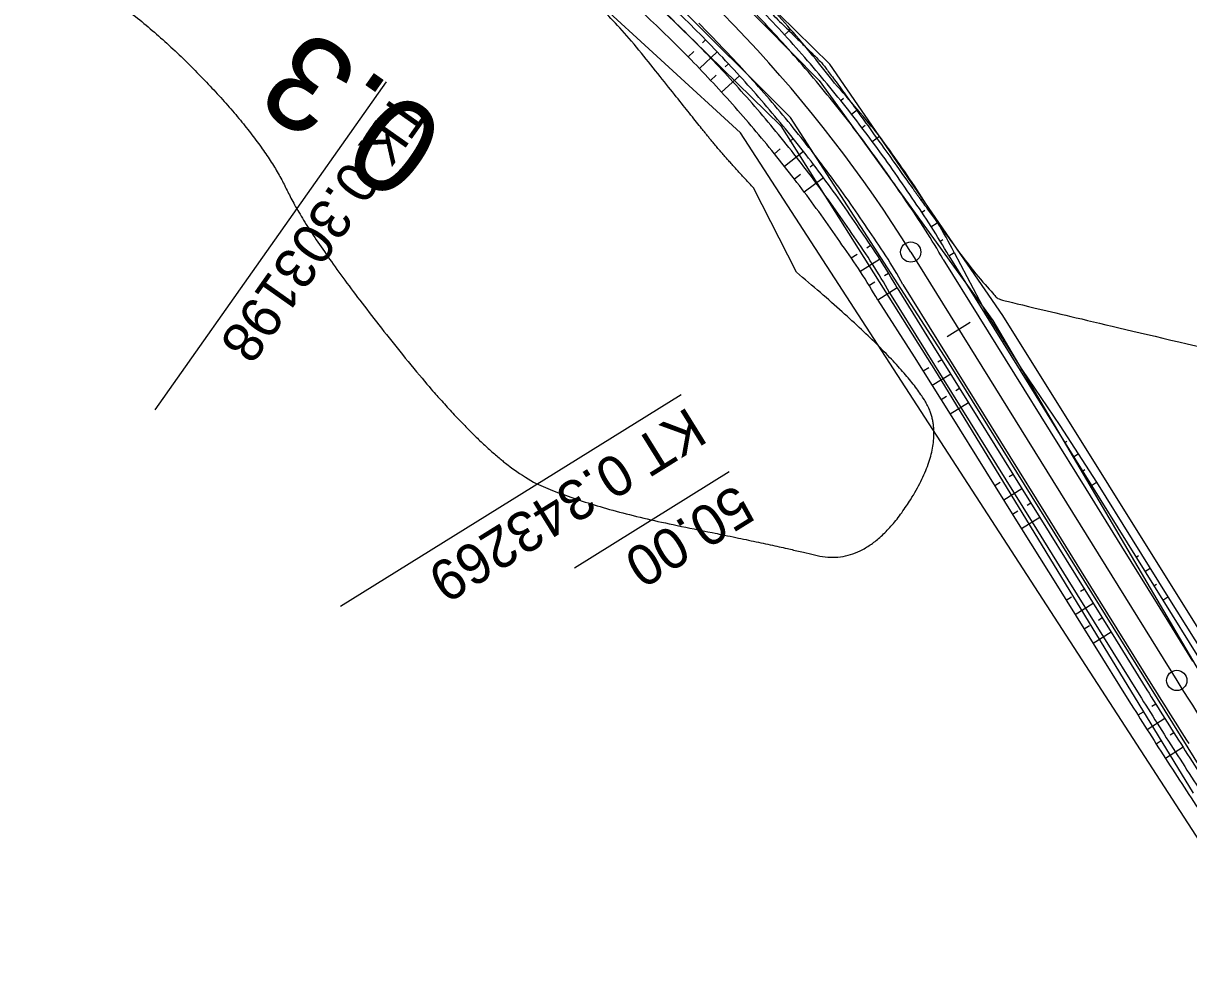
# Model space of a CAD drawing. Extents: x -495905 to -478420, y -1113297 to -1107716.
# Drawn here: x -480763.1 to -480676.8, y -1112853.9 to -1112783.6 of the extents above; entities that cross this region are included whole.
import ezdxf

# ---------------------------------------------------------------- set-up
doc = ezdxf.new("R2010")
doc.units = 0
for name, color, linetype in [('03_PC_OBJEKTY_NÁVRH_PR', 7, 'Continuous'), ('2D_VRSTEVNICE', 7, 'Continuous'), ('C13_HATCH_SLOPE_L', 7, 'Continuous'), ('C13_HATCH_SLOPE_R', 7, 'Continuous'), ('C13_HECTOMETRY', 7, 'Continuous'), ('C13_HLBODY', 7, 'Continuous'), ('C13_HRANA_TELESO', 7, 'Continuous'), ('C13_KORUNA', 7, 'Continuous'), ('C13_OSA', 7, 'Continuous'), ('C13_PRIKOP', 7, 'Continuous'), ('C13_STANICENI', 7, 'Continuous'), ('C13_VOZOVKA', 7, 'Continuous'), ('C13_ZPEVKRAJ', 7, 'Continuous'), ('zamereni', 7, 'Continuous')]:
    doc.layers.add(name, color=color, linetype=linetype)

msp = doc.modelspace()

# ---------------------------------------------------------------- linework, layer by layer
at = {"layer": '03_PC_OBJEKTY_NÁVRH_PR'}
msp.add_lwpolyline([(-480609.77, -1112943.11), (-480632.07, -1112906.22), (-480673.38, -1112848.12), (-480710, -1112791.67), (-480726.8, -1112776.25), (-480787.1, -1112736.87), (-480856.49, -1112680.15), (-480961.12, -1112584.33)], dxfattribs=at)
at = {"layer": '2D_VRSTEVNICE'}
msp.add_lwpolyline([(-480705.856, -1112801.984), (-480709.033, -1112795.743)], dxfattribs=at)
for points in [[(-480709.033, -1112795.743), (-480711.34, -1112793.268), (-480713.633, -1112790.394), (-480720.471, -1112781.825), (-480725.405, -1112779.135), (-480733.412, -1112773.693), (-480743.366, -1112768.241), (-480741.88, -1112762.294), (-480747.701, -1112758.269), (-480747.756, -1112758.23), (-480750.594, -1112756.204), (-480750.824, -1112756.04), (-480756.969, -1112751.652), (-480757.518, -1112751.261), (-480777.842, -1112736.752), (-480779.086, -1112735.864), (-480779.423, -1112735.624), (-480783.574, -1112732.66), (-480788.757, -1112728.437)], [(-480809.7, -1112754.66), (-480782.38, -1112767.95), (-480764.439, -1112762.001), (-480767.966, -1112775.097), (-480755.599, -1112781.764), (-480745.361, -1112792.13), (-480741.836, -1112799.587), (-480728.591, -1112816.095), (-480720.89, -1112819.47), (-480707.793, -1112822.109), (-480700.856, -1112823.771), (-480695.042, -1112815.483), (-480696.658, -1112809.693), (-480705.856, -1112801.984)], [(-480714.503, -1112776.18), (-480704.556, -1112785.911), (-480703.578, -1112786.898), (-480691.565, -1112803.76), (-480689.92, -1112804.25), (-480656.601, -1112812.049)]]:
    msp.add_open_spline(points, degree=2, dxfattribs=at)
at = {"layer": 'C13_HATCH_SLOPE_L'}
for p, q in [((-480706.731, -1112784.421), (-480706.281, -1112784.012)), ((-480702.578, -1112789.277), (-480702.376, -1112789.116)), ((-480702.175, -1112788.954), (-480702.175, -1112788.954)), ((-480701.784, -1112790.279), (-480701.339, -1112789.931)), ((-480701.003, -1112791.291), (-480700.759, -1112791.105)), ((-480700.515, -1112790.919), (-480700.515, -1112790.919)), ((-480700.235, -1112792.312), (-480699.702, -1112791.917)), ((-480696.089, -1112797.235), (-480696.089, -1112797.235)), ((-480696.588, -1112797.559), (-480696.338, -1112797.397)), ((-480695.899, -1112798.635), (-480695.429, -1112798.339)), ((-480695.227, -1112799.71), (-480695.008, -1112799.574)), ((-480694.79, -1112799.438), (-480694.79, -1112799.438)), ((-480694.567, -1112800.772), (-480694.165, -1112800.522)), ((-480691.269, -1112806.08), (-480691.218, -1112806.048)), ((-480691.166, -1112806.016), (-480691.166, -1112806.016)), ((-480690.609, -1112807.142), (-480690.5, -1112807.074)), ((-480689.949, -1112808.204), (-480689.892, -1112808.168)), ((-480689.834, -1112808.132), (-480689.834, -1112808.132)), ((-480689.29, -1112809.266), (-480689.168, -1112809.19)), ((-480685.991, -1112814.574), (-480685.831, -1112814.474)), ((-480685.671, -1112814.375), (-480685.671, -1112814.375)), ((-480685.331, -1112815.636), (-480684.992, -1112815.425)), ((-480684.672, -1112816.698), (-480684.492, -1112816.586)), ((-480684.313, -1112816.475), (-480684.313, -1112816.475)), ((-480684.012, -1112817.759), (-480683.634, -1112817.524)), ((-480680.713, -1112823.068), (-480680.52, -1112822.948)), ((-480680.328, -1112822.829), (-480680.328, -1112822.829)), ((-480680.054, -1112824.13), (-480679.667, -1112823.89)), ((-480679.394, -1112825.191), (-480679.2, -1112825.07)), ((-480679.006, -1112824.95), (-480679.006, -1112824.95)), ((-480678.734, -1112826.253), (-480678.345, -1112826.011))]:
    msp.add_line(p, q, dxfattribs=at)
at = {"layer": 'C13_HATCH_SLOPE_R'}
for p, q in [((-480712.576, -1112784.788), (-480712.814, -1112785.022)), ((-480713.46, -1112785.655), (-480713.867, -1112786.055)), ((-480711.725, -1112785.665), (-480713.032, -1112786.916)), ((-480710.886, -1112786.553), (-480711.13, -1112786.78)), ((-480711.79, -1112787.398), (-480712.207, -1112787.787)), ((-480710.058, -1112787.451), (-480711.394, -1112788.668)), ((-480707.047, -1112792.863), (-480707.486, -1112793.215)), ((-480706.088, -1112792.094), (-480706.348, -1112792.302)), ((-480705.329, -1112793.051), (-480706.737, -1112794.152)), ((-480704.583, -1112794.019), (-480704.848, -1112794.221)), ((-480705.556, -1112794.761), (-480706, -1112795.099)), ((-480703.848, -1112794.995), (-480705.274, -1112796.054)), ((-480701.366, -1112800.664), (-480701.812, -1112800.953)), ((-480700.362, -1112800.011), (-480700.642, -1112800.192)), ((-480699.702, -1112801.039), (-480701.154, -1112801.957)), ((-480699.049, -1112802.085), (-480699.332, -1112802.261)), ((-480700.056, -1112802.711), (-480700.498, -1112802.985)), ((-480698.39, -1112803.147), (-480699.828, -1112804.04)), ((-480695.091, -1112808.455), (-480695.374, -1112808.631)), ((-480696.062, -1112809.059), (-480696.468, -1112809.311)), ((-480694.431, -1112809.517), (-480695.802, -1112810.369)), ((-480693.772, -1112810.579), (-480694.055, -1112810.755)), ((-480694.738, -1112811.179), (-480695.137, -1112811.427)), ((-480693.112, -1112811.641), (-480694.471, -1112812.485)), ((-480689.813, -1112816.949), (-480690.096, -1112817.125)), ((-480690.772, -1112817.545), (-480691.165, -1112817.789)), ((-480689.154, -1112818.011), (-480690.506, -1112818.851)), ((-480689.454, -1112819.668), (-480689.847, -1112819.913)), ((-480688.494, -1112819.073), (-480688.777, -1112819.248)), ((-480687.834, -1112820.134), (-480689.187, -1112820.975)), ((-480684.536, -1112825.443), (-480684.819, -1112825.619)), ((-480685.488, -1112826.035), (-480685.875, -1112826.275)), ((-480683.876, -1112826.505), (-480685.212, -1112827.335)), ((-480684.166, -1112828.156), (-480684.549, -1112828.395)), ((-480683.216, -1112827.566), (-480683.499, -1112827.742)), ((-480682.556, -1112828.628), (-480683.887, -1112829.455)), ((-480679.255, -1112833.941), (-480679.538, -1112834.118)), ((-480680.194, -1112834.528), (-480680.569, -1112834.761)), ((-480678.585, -1112835.007), (-480679.893, -1112835.832)), ((-480677.912, -1112836.072), (-480678.193, -1112836.25)), ((-480678.844, -1112836.664), (-480679.213, -1112836.9)), ((-480677.233, -1112837.133), (-480678.529, -1112837.964))]:
    msp.add_line(p, q, dxfattribs=at)
at = {"layer": 'C13_HLBODY'}
for p, q in [((-480736.232, -1112787.884), (-480753.346, -1112812.157)), ((-480714.38, -1112811.045), (-480739.606, -1112826.72))]:
    msp.add_line(p, q, dxfattribs=at)
for centre in [(-480697.392, -1112800.489), (-480677.695, -1112832.188)]:
    msp.add_circle(centre, 0.75, dxfattribs=at)
at = {"layer": 'C13_HRANA_TELESO'}
for p, q in [((-480694.165, -1112800.522), (-480691.832, -1112804.958)), ((-480699.828, -1112804.04), (-480697.134, -1112808.253)), ((-480691.832, -1112804.958), (-480689.168, -1112809.19)), ((-480697.134, -1112808.253), (-480694.471, -1112812.485)), ((-480689.168, -1112809.19), (-480686.35, -1112813.326)), ((-480694.471, -1112812.485), (-480691.824, -1112816.727)), ((-480686.35, -1112813.326), (-480683.634, -1112817.524)), ((-480691.824, -1112816.727), (-480689.187, -1112820.975)), ((-480683.634, -1112817.524), (-480680.99, -1112821.768)), ((-480689.187, -1112820.975), (-480686.537, -1112825.215)), ((-480680.99, -1112821.768), (-480678.345, -1112826.011)), ((-480686.537, -1112825.215), (-480683.887, -1112829.455)), ((-480678.345, -1112826.011), (-480675.701, -1112830.255)), ((-480683.887, -1112829.455), (-480681.237, -1112833.695))]:
    msp.add_line(p, q, dxfattribs=at)
for centre, radius, start, end in [((-480783.464, -1112852.063), 102.899, 41.4022, 44.26736), ((-480782.424, -1112853.178), 95.944, 45.11065, 47.97544), ((-480784.143, -1112851.115), 102.788, 37.88976, 40.75562), ((-480782.308, -1112853.29), 95.942, 42.34173, 45.20652), ((-480779.855, -1112856.31), 102.815, 38.77783, 41.6447), ((-480782.2, -1112853.417), 95.947, 39.57666, 42.44146), ((-480782.642, -1112852.822), 102.9, 33.42609, 36.29092), ((-480782.068, -1112853.601), 95.963, 36.8472, 39.71202), ((-480781.927, -1112853.835), 95.991, 34.14437, 37.00923), ((-480739.666, -1112824.522), 51.443, 27.81079, 33.48765), ((-480741.349, -1112828.131), 48.004, 30.12239, 35.93747), ((-479910.26, -1112347.705), 911.368, 212.2255, 212.543347), ((-480423.024, -1112673.635), 303.787, 212.74733, 213.70226)]:
    msp.add_arc(centre, radius, start, end, dxfattribs=at)
at = {"layer": 'C13_KORUNA'}
for p, q in [((-480694.567, -1112800.772), (-480691.929, -1112805.019)), ((-480698.39, -1112803.147), (-480695.751, -1112807.394)), ((-480691.929, -1112805.019), (-480689.29, -1112809.266)), ((-480695.751, -1112807.394), (-480693.112, -1112811.641)), ((-480689.29, -1112809.266), (-480686.651, -1112813.512)), ((-480693.112, -1112811.641), (-480690.473, -1112815.887)), ((-480686.651, -1112813.512), (-480684.012, -1112817.759)), ((-480690.473, -1112815.887), (-480687.834, -1112820.134)), ((-480684.012, -1112817.759), (-480681.373, -1112822.006)), ((-480687.834, -1112820.134), (-480685.195, -1112824.381)), ((-480681.373, -1112822.006), (-480678.734, -1112826.253)), ((-480685.195, -1112824.381), (-480682.556, -1112828.628)), ((-480678.734, -1112826.253), (-480676.095, -1112830.5)), ((-480682.556, -1112828.628), (-480679.917, -1112832.875))]:
    msp.add_line(p, q, dxfattribs=at)
for centre, radius, start, end in [((-480782.33, -1112853.267), 97.75, 45.18774, 48.05253), ((-480782.33, -1112853.267), 102.25, 42.32296, 45.18774), ((-480782.33, -1112853.267), 97.75, 42.32295, 45.18774), ((-480782.33, -1112853.267), 102.25, 39.45817, 42.32296), ((-480782.33, -1112853.267), 97.75, 39.45817, 42.32296), ((-480782.33, -1112853.267), 102.25, 36.59338, 39.45817), ((-480782.33, -1112853.267), 97.75, 36.59338, 39.45817), ((-480782.33, -1112853.267), 102.25, 33.72859, 36.59338), ((-480782.33, -1112853.267), 97.75, 33.72859, 36.59338), ((-480739.008, -1112826.047), 51.125, 29.62846, 35.3164), ((-480740.897, -1112827.269), 48.875, 29.57422, 35.35155), ((-479911.523, -1112351.455), 906.75, 212.068244, 212.386272), ((-480422.881, -1112673.855), 302.25, 212.69777, 213.6527)]:
    msp.add_arc(centre, radius, start, end, dxfattribs=at)
at = {"layer": 'C13_OSA'}
msp.add_line((-480697.392, -1112800.489), (-480677.695, -1112832.188), dxfattribs=at)
for centre, radius, start, end in [((-480782.33, -1112853.267), 100, 31.85534, 54.81438), ((-480422.88, -1112673.855), 300, 211.85533, 216.27914)]:
    msp.add_arc(centre, radius, start, end, dxfattribs=at)
at = {"layer": 'C13_PRIKOP'}
for p, q in [((-480698.956, -1112803.498), (-480696.317, -1112807.745)), ((-480696.317, -1112807.745), (-480693.678, -1112811.992)), ((-480693.678, -1112811.992), (-480691.039, -1112816.239)), ((-480691.039, -1112816.239), (-480688.4, -1112820.486)), ((-480688.4, -1112820.486), (-480685.761, -1112824.733)), ((-480685.761, -1112824.733), (-480683.122, -1112828.98)), ((-480683.122, -1112828.98), (-480680.484, -1112833.227))]:
    msp.add_line(p, q, dxfattribs=at)
for centre, radius, start, end in [((-480782.33, -1112853.267), 97.084, 45.18774, 48.05253), ((-480782.33, -1112853.267), 97.084, 42.32295, 45.18774), ((-480782.33, -1112853.267), 97.084, 39.45816, 42.32295), ((-480782.33, -1112853.267), 97.084, 36.59338, 39.45817), ((-480782.33, -1112853.267), 97.084, 33.72859, 36.59338), ((-480741.177, -1112827.45), 48.542, 29.56579, 35.35706), ((-479910.396, -1112350.744), 908.749, 212.068381, 212.386328), ((-480422.881, -1112673.855), 302.916, 212.69777, 213.6527)]:
    msp.add_arc(centre, radius, start, end, dxfattribs=at)
at = {"layer": 'C13_STANICENI'}
for p, q in [((-480694.689, -1112806.734), (-480692.99, -1112805.678)), ((-480710.827, -1112816.762), (-480722.294, -1112823.887))]:
    msp.add_line(p, q, dxfattribs=at)
at = {"layer": 'C13_VOZOVKA'}
for p, q in [((-480694.992, -1112801.036), (-480692.353, -1112805.283)), ((-480697.965, -1112802.883), (-480695.326, -1112807.13)), ((-480692.353, -1112805.283), (-480689.714, -1112809.529)), ((-480695.326, -1112807.13), (-480692.687, -1112811.377)), ((-480689.714, -1112809.529), (-480687.075, -1112813.776)), ((-480692.687, -1112811.377), (-480690.048, -1112815.624)), ((-480687.075, -1112813.776), (-480684.437, -1112818.023)), ((-480690.048, -1112815.624), (-480687.409, -1112819.87)), ((-480684.437, -1112818.023), (-480681.798, -1112822.27)), ((-480687.409, -1112819.87), (-480684.771, -1112824.117)), ((-480681.798, -1112822.27), (-480679.159, -1112826.517)), ((-480684.771, -1112824.117), (-480682.132, -1112828.364)), ((-480679.159, -1112826.517), (-480676.52, -1112830.764)), ((-480682.132, -1112828.364), (-480679.493, -1112832.611))]:
    msp.add_line(p, q, dxfattribs=at)
for centre, radius, start, end in [((-480782.33, -1112853.267), 101.75, 42.32296, 45.18774), ((-480782.33, -1112853.267), 98.25, 42.32295, 45.18774), ((-480782.33, -1112853.267), 101.75, 39.45817, 42.32296), ((-480782.33, -1112853.267), 98.25, 39.45817, 42.32296), ((-480782.33, -1112853.267), 101.75, 36.59338, 39.45817), ((-480782.33, -1112853.267), 98.25, 36.59338, 39.45817), ((-480782.33, -1112853.267), 101.75, 33.72859, 36.59338), ((-480782.33, -1112853.267), 98.25, 33.72859, 36.59338), ((-480739.218, -1112826.182), 50.875, 29.62266, 35.32014), ((-480740.687, -1112827.133), 49.125, 29.58048, 35.34747), ((-479912.368, -1112351.989), 905.25, 212.068142, 212.386231)]:
    msp.add_arc(centre, radius, start, end, dxfattribs=at)
at = {"layer": 'C13_ZPEVKRAJ'}
for p, q in [((-480694.992, -1112801.036), (-480692.353, -1112805.283)), ((-480697.965, -1112802.883), (-480695.326, -1112807.13)), ((-480692.353, -1112805.283), (-480689.714, -1112809.529)), ((-480695.326, -1112807.13), (-480692.687, -1112811.377)), ((-480689.714, -1112809.529), (-480687.075, -1112813.776)), ((-480692.687, -1112811.377), (-480690.048, -1112815.624)), ((-480687.075, -1112813.776), (-480684.437, -1112818.023)), ((-480690.048, -1112815.624), (-480687.409, -1112819.87)), ((-480684.437, -1112818.023), (-480681.798, -1112822.27)), ((-480687.409, -1112819.87), (-480684.771, -1112824.117)), ((-480681.798, -1112822.27), (-480679.159, -1112826.517)), ((-480684.771, -1112824.117), (-480682.132, -1112828.364)), ((-480679.159, -1112826.517), (-480676.52, -1112830.764)), ((-480682.132, -1112828.364), (-480679.493, -1112832.611))]:
    msp.add_line(p, q, dxfattribs=at)
for centre, radius, start, end in [((-480782.33, -1112853.267), 101.75, 42.32296, 45.18774), ((-480782.33, -1112853.267), 98.25, 42.32295, 45.18774), ((-480782.33, -1112853.267), 101.75, 39.45817, 42.32296), ((-480782.33, -1112853.267), 98.25, 39.45817, 42.32296), ((-480782.33, -1112853.267), 101.75, 36.59338, 39.45817), ((-480782.33, -1112853.267), 98.25, 36.59338, 39.45817), ((-480782.33, -1112853.267), 101.75, 33.72859, 36.59338), ((-480782.33, -1112853.267), 98.25, 33.72859, 36.59338), ((-480739.218, -1112826.182), 50.875, 29.62266, 35.32014), ((-480740.687, -1112827.133), 49.125, 29.58048, 35.34747), ((-479912.368, -1112351.989), 905.25, 212.068142, 212.386231)]:
    msp.add_arc(centre, radius, start, end, dxfattribs=at)
at = {"layer": 'zamereni'}
for p, q in [((-480703.38, -1112786.6), (-480717.03, -1112773.17)), ((-480717.82, -1112773.98), (-480704.17, -1112787.79)), ((-480706.29, -1112790.53), (-480720.03, -1112776.84)), ((-480720.74, -1112777.72), (-480707.01, -1112791.16)), ((-480690.58, -1112805.19), (-480703.38, -1112786.6)), ((-480704.17, -1112787.79), (-480691.32, -1112805.56)), ((-480707.01, -1112791.16), (-480695.43, -1112809.49)), ((-480694.4, -1112808.95), (-480706.29, -1112790.53)), ((-480691.32, -1112805.56), (-480672.09, -1112838.26)), ((-480670.56, -1112837.22), (-480690.58, -1112805.19)), ((-480675.27, -1112839.72), (-480694.4, -1112808.95)), ((-480695.43, -1112809.49), (-480676.49, -1112840.53))]:
    msp.add_line(p, q, dxfattribs=at)

# ---------------------------------------------------------------- texts
at = {"layer": 'C13_HECTOMETRY'}
msp.add_text('0.3', height=7, rotation=144.76876, dxfattribs=at).set_placement((-480731.46, -1112791.257))
at = {"layer": 'C13_HLBODY'}
for s, rotation, p in [('TK 0.303198', 234.81438, (-480735.414, -1112788.459)), ('KT 0.343269', 211.85534, (-480713.851, -1112811.894))]:
    msp.add_text(s, height=2.999, rotation=rotation, dxfattribs=at).set_placement(p)
at = {"layer": 'C13_STANICENI'}
msp.add_text('50.00', height=3, rotation=211.85534, dxfattribs=at).set_placement((-480710.299, -1112817.611))

doc.saveas('drawing.dxf')
